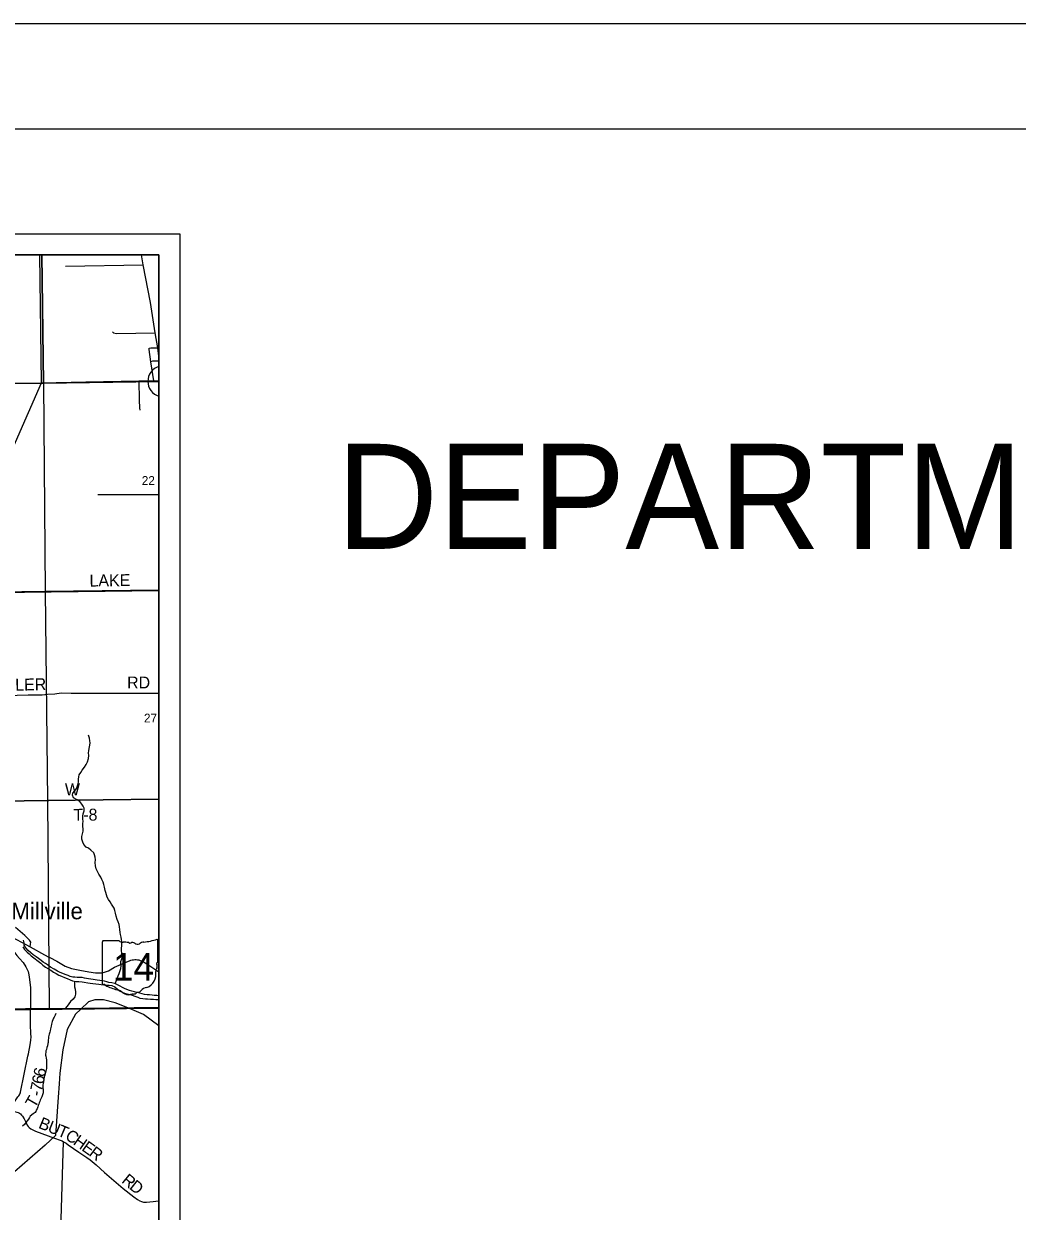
# Model space of a CAD drawing. Extents: x 0 to 34, y 0 to 22.
# Drawn here: x 8.26 to 12.99, y 16.35 to 22 of the extents above; entities that cross this region are included whole.
import ezdxf

# ---------------------------------------------------------------- set-up
doc = ezdxf.new("R2010")
doc.units = 0
for name, color, linetype in [('GM_X_County_Road', 7, 'Continuous'), ('GM_X_Minor_River', 7, 'Continuous'), ('GM_X_Rail_Line', 7, 'Continuous'), ('GM_X_Section', 7, 'Continuous'), ('GM_X_Section_Text', 7, 'Continuous'), ('GM_X_State_Location', 7, 'Continuous'), ('GM_X_State_Route', 7, 'Continuous'), ('GM_X_State_Shield', 7, 'Continuous'), ('GM_X_Township_Road', 7, 'Continuous'), ('GM_X_Township_Road_Text', 7, 'Continuous'), ('GM_X_Unincorporated_Text', 7, 'Continuous'), ('SH_Border', 7, 'Continuous'), ('SH_Cut_Line', 7, 'Continuous'), ('SH_Data', 7, 'Continuous'), ('SH_Text', 7, 'Continuous')]:
    doc.layers.add(name, color=color, linetype=linetype)

msp = doc.modelspace()

# ---------------------------------------------------------------- linework, layer by layer
at = {"layer": 'GM_X_County_Road'}
for points in [[(8.9, 20.4176), (8.8952, 20.4576), (8.8827, 20.5279), (8.8607, 20.6726), (8.8255, 20.8525), (8.8168, 20.9)], [(7.8996, 19.2895), (8.1438, 19.8412), (8.341, 20.2911)], [(8.2872, 17.6056), (8.2893, 17.6184), (8.2907, 17.6268), (8.2847, 17.6373), (8.2615, 17.6593), (8.2181, 17.6976)]]:
    msp.add_lwpolyline(points, dxfattribs=at)
at = {"layer": 'GM_X_Minor_River'}
for points in [[(8.6919, 17.4296), (8.7068, 17.4673), (8.7112, 17.4787), (8.7159, 17.4921), (8.7192, 17.5024), (8.7201, 17.5153), (8.7192, 17.5252), (8.719, 17.5358), (8.7233, 17.5477), (8.7269, 17.561), (8.7244, 17.5754), (8.7215, 17.5875), (8.7221, 17.5982), (8.7238, 17.6096), (8.7244, 17.6202), (8.7239, 17.6305), (8.7222, 17.6403), (8.7205, 17.6506), (8.718, 17.6634), (8.7167, 17.674), (8.715, 17.6873), (8.7132, 17.7002), (8.7111, 17.7112), (8.7071, 17.7244), (8.7024, 17.7346), (8.6968, 17.7519), (8.6943, 17.7652), (8.691, 17.7784), (8.6871, 17.7886), (8.6812, 17.7988), (8.675, 17.8086), (8.6684, 17.8187), (8.661, 17.83), (8.6543, 17.8416), (8.6503, 17.8526), (8.6471, 17.8632), (8.6443, 17.873), (8.6414, 17.8885), (8.6385, 17.9025), (8.6349, 17.9131), (8.629, 17.9259), (8.6243, 17.9361), (8.6149, 17.9511), (8.6086, 17.9632), (8.6023, 17.9767), (8.5983, 17.99), (8.5969, 18.0063), (8.5982, 18.02), (8.5969, 18.0321), (8.5944, 18.0431), (8.5904, 18.0529), (8.5758, 18.0659), (8.5646, 18.0741), (8.5547, 18.0804), (8.5427, 18.0924), (8.5376, 18.104), (8.5339, 18.118), (8.5337, 18.1306), (8.5362, 18.1424), (8.539, 18.1553), (8.5399, 18.1675), (8.5386, 18.1785), (8.5388, 18.1922), (8.5394, 18.2024), (8.5388, 18.215), (8.5389, 18.2279), (8.5403, 18.2382), (8.5438, 18.253), (8.544, 18.2648), (8.5404, 18.2746), (8.5342, 18.2844), (8.5234, 18.2975), (8.5111, 18.3053), (8.4942, 18.3141), (8.4887, 18.3266), (8.4904, 18.3368), (8.5005, 18.348), (8.5079, 18.3592), (8.5134, 18.3714), (8.5155, 18.3809), (8.5169, 18.3912), (8.5178, 18.4041), (8.5184, 18.414), (8.5212, 18.4243), (8.5279, 18.4358), (8.5357, 18.4458), (8.5461, 18.4601), (8.5535, 18.4731), (8.5605, 18.4857), (8.5655, 18.5014), (8.566, 18.5155), (8.5655, 18.528), (8.566, 18.539), (8.5689, 18.5493), (8.5721, 18.5646), (8.5726, 18.5756), (8.5717, 18.5866), (8.5692, 18.5979), (8.5644, 18.613)], [(8.252, 17.6048), (8.2598, 17.5924), (8.2726, 17.5793), (8.2826, 17.5712)], [(8.2665, 17.6005), (8.2595, 17.6137), (8.2581, 17.6239), (8.2564, 17.6368)], [(8.9, 17.3713), (8.8902, 17.3727), (8.8785, 17.374), (8.8678, 17.375), (8.856, 17.3759), (8.8446, 17.3773), (8.8317, 17.3789), (8.8203, 17.381), (8.8088, 17.3839), (8.7959, 17.3871), (8.7848, 17.3907), (8.7718, 17.3943), (8.76, 17.3975), (8.7482, 17.4019), (8.7371, 17.4062), (8.7275, 17.411), (8.716, 17.4173), (8.7037, 17.4243), (8.6907, 17.4302), (8.6763, 17.4333), (8.6626, 17.4358), (8.653, 17.4379), (8.6416, 17.4415), (8.6309, 17.4432), (8.6191, 17.4446), (8.6069, 17.4466), (8.5967, 17.448), (8.5868, 17.4497), (8.5757, 17.4514), (8.5655, 17.4528), (8.5559, 17.4545), (8.5457, 17.4566), (8.5358, 17.4584), (8.5255, 17.4593), (8.5118, 17.4599), (8.5004, 17.4601), (8.4902, 17.461), (8.478, 17.4643), (8.4684, 17.4679), (8.4539, 17.4737), (8.4428, 17.4785), (8.4306, 17.4832), (8.4168, 17.4887), (8.4015, 17.4987), (8.3846, 17.5087), (8.37, 17.5187), (8.3604, 17.5253), (8.35, 17.5316), (8.3393, 17.5406), (8.3269, 17.5502), (8.3154, 17.5573), (8.302, 17.5673), (8.2904, 17.5766), (8.2781, 17.5878), (8.2665, 17.6005)], [(8.2826, 17.5712), (8.2922, 17.5626), (8.3049, 17.5525), (8.326, 17.5362), (8.338, 17.5273), (8.3484, 17.5176), (8.361, 17.509), (8.3752, 17.5009), (8.3852, 17.4939), (8.3983, 17.485), (8.4105, 17.4779), (8.4239, 17.471), (8.4373, 17.4655), (8.4507, 17.4596), (8.4633, 17.4545), (8.4782, 17.4483), (8.4893, 17.4436), (8.5057, 17.4404), (8.5194, 17.4395), (8.5353, 17.4386), (8.5452, 17.4376), (8.5624, 17.4341), (8.5734, 17.432), (8.586, 17.4307), (8.6008, 17.4291), (8.6137, 17.4278), (8.6255, 17.4257), (8.6381, 17.4236), (8.6537, 17.4227), (8.6639, 17.4221), (8.6769, 17.4208), (8.6902, 17.415), (8.7026, 17.4038), (8.7122, 17.3952), (8.7256, 17.3897), (8.737, 17.385), (8.7485, 17.3814), (8.763, 17.3774), (8.7737, 17.3746), (8.7859, 17.3702), (8.8008, 17.3648), (8.8103, 17.3615), (8.8237, 17.3587), (8.8366, 17.3578), (8.8461, 17.3571), (8.8609, 17.3563), (8.8753, 17.3557), (8.8852, 17.3551), (8.8974, 17.3538), (8.9, 17.3532)], [(8.4981, 17.4419), (8.4985, 17.4152), (8.501, 17.4031), (8.5031, 17.3899), (8.5025, 17.38), (8.4997, 17.3674), (8.4919, 17.3566), (8.4799, 17.3443), (8.471, 17.3331), (8.4629, 17.322), (8.4539, 17.3112)], [(8.4099, 17.2872), (8.4098, 17.2871), (8.4066, 17.2795), (8.4018, 17.2702), (8.3982, 17.2652), (8.3953, 17.2583), (8.3924, 17.2502), (8.3903, 17.2426), (8.3896, 17.2376), (8.3876, 17.2269), (8.3854, 17.2212), (8.3844, 17.2151), (8.3827, 17.2052), (8.3814, 17.1987), (8.3785, 17.1895), (8.376, 17.183), (8.3754, 17.1769), (8.3748, 17.1689), (8.3734, 17.1624), (8.3731, 17.1563), (8.3725, 17.1502), (8.3715, 17.1441), (8.3706, 17.1345), (8.3673, 17.1257), (8.3645, 17.1162), (8.3627, 17.1097), (8.3614, 17.102), (8.3604, 17.0952), (8.3609, 17.0891), (8.3618, 17.0842), (8.3638, 17.0758), (8.3652, 17.0667), (8.3657, 17.0595), (8.365, 17.0382), (8.3653, 17.0253), (8.3611, 17.0066), (8.3593, 17.0016), (8.3568, 16.9939), (8.3543, 16.9859), (8.3527, 16.9729), (8.3503, 16.9615), (8.3493, 16.9554), (8.3476, 16.9462), (8.347, 16.9397), (8.3474, 16.9348), (8.3488, 16.9257), (8.3501, 16.9185), (8.3487, 16.9097), (8.3427, 16.8902), (8.3387, 16.8821), (8.3347, 16.8752), (8.3329, 16.8694), (8.3308, 16.8625), (8.3282, 16.8564), (8.325, 16.8499), (8.3232, 16.8434), (8.3204, 16.8346), (8.3167, 16.8272), (8.3146, 16.8219), (8.3113, 16.8169), (8.3023, 16.8098), (8.2878, 16.7988), (8.2841, 16.7931), (8.279, 16.7853), (8.2664, 16.768), (8.2598, 16.7587), (8.2509, 16.7513)]]:
    msp.add_lwpolyline(points, dxfattribs=at)
at = {"layer": 'GM_X_Rail_Line'}
for points in [[(7.4754, 17.3006), (8.2882, 17.3064), (8.9, 17.3138), (8.9, 20.9), (5.4984, 20.9)], [(8.5286, 17.3089), (8.5035, 17.2853), (8.4632, 17.2119), (8.4437, 17.114), (8.4289, 17.004), (8.426, 16.9527), (8.4215, 16.8896), (8.4085, 16.7064), (8.3593, 16.6612), (8.0289, 16.3753)], [(8.76, 17.3117), (8.6923, 17.3381), (8.6373, 17.3524), (8.595, 17.353), (8.5653, 17.3434), (8.5286, 17.3089)], [(8.9, 17.2297), (8.8277, 17.2837), (8.76, 17.3117)]]:
    msp.add_lwpolyline(points, dxfattribs=at)
msp.add_lwpolyline([(5.5619, 14.1), (8.9, 14.1), (8.9, 17.3138), (8.2882, 17.3064), (7.4754, 17.3006), (7.4757, 17.0495), (7.4723, 16.4951), (7.4818, 15.827), (7.482, 15.8179), (7.4834, 15.2992), (7.3416, 15.297), (6.5709, 15.2859), (6.3575, 15.2833), (5.5569, 15.2761), (5.5579, 15.2049), (5.5588, 15.1747), (5.5581, 14.9676), (5.5583, 14.9347), (5.5595, 14.6439), (5.5615, 14.2414), (5.5608, 14.205)], close=True, dxfattribs=at)
at = {"layer": 'GM_X_Section'}
for points in [[(7.3448, 20.2776), (8.3505, 20.2885), (8.3591, 19.2972), (7.3562, 19.2826)], [(7.3562, 19.2826), (8.3591, 19.2972), (8.3698, 18.3026), (7.3737, 18.2882)], [(7.3737, 18.2882), (8.3698, 18.3026), (8.3784, 17.3112), (7.4756, 17.2983), (7.3918, 17.2975)]]:
    msp.add_lwpolyline(points, close=True, dxfattribs=at)
at = {"layer": 'GM_X_State_Route'}
for points in [[(8.5527, 20.295), (8.8047, 20.2996), (8.8761, 20.3006), (8.9, 20.2998)], [(6.5764, 20.2689), (6.689, 20.2704), (8.341, 20.2911), (8.5527, 20.295)], [(7.9769, 17.6625), (7.989, 17.6724), (8.0066, 17.6879), (8.0232, 17.6976), (8.0383, 17.7032), (8.0648, 17.7086), (8.0877, 17.7051), (8.1129, 17.6987), (8.1806, 17.6629), (8.2872, 17.6056)], [(8.2872, 17.6056), (8.3557, 17.5677), (8.3765, 17.5566), (8.3803, 17.5546)], [(8.3803, 17.5546), (8.4144, 17.5364), (8.4543, 17.5134), (8.4846, 17.5025), (8.5246, 17.4937), (8.5669, 17.4867), (8.5978, 17.4819), (8.6132, 17.481), (8.6301, 17.4817), (8.6458, 17.4859), (8.6596, 17.4916), (8.6883, 17.5077), (8.7475, 17.5333), (8.7598, 17.5385), (8.7663, 17.5411), (8.7729, 17.5428), (8.7791, 17.5438), (8.7857, 17.5444), (8.7923, 17.5445), (8.7987, 17.544), (8.8056, 17.5426), (8.8116, 17.5407), (8.8216, 17.5364), (8.8424, 17.5242), (8.9, 17.486)]]:
    msp.add_lwpolyline(points, dxfattribs=at)
at = {"layer": 'GM_X_State_Shield'}
for p, q in [((8.631, 17.6295), (8.631, 17.4294)), ((8.7109, 17.633), (8.6336, 17.633)), ((8.8947, 17.5332), (8.8947, 17.6379)), ((8.8947, 17.5333), (8.8947, 17.5332))]:
    msp.add_line(p, q, dxfattribs=at)
for points in [[(8.343, 20.9), (7.3363, 20.9), (7.3448, 20.2776), (8.3505, 20.2885)], [(8.9, 20.2971), (8.9, 20.9), (8.343, 20.9), (8.3505, 20.2885)], [(8.9, 19.3038), (8.9, 20.2971), (8.3505, 20.2885), (8.3591, 19.2972)], [(8.9, 18.3087), (8.9, 19.3038), (8.3591, 19.2972), (8.3698, 18.3026)], [(8.9, 17.3185), (8.9, 18.3087), (8.3698, 18.3026), (8.3784, 17.3112), (8.4281, 17.3119)]]:
    msp.add_lwpolyline(points, close=True, dxfattribs=at)
for centre, radius, start, end in [((8.8008, 17.9058), 0.2796, 275.8445, 288.9065), ((8.8918, 17.6383), 0.00294, 351.8621, 97.738), ((8.6341, 17.6299), 0.00305, 98.1301, 188.1301), ((8.7292, 17.6562), 0.0296, 231.6195, 271.1119), ((8.7391, 17.5206), 0.1064, 80.4867, 94.9883), ((8.7632, 17.631), 0.00855, 219.7921, 297.1024), ((8.7758, 17.6078), 0.0178, 54.4667, 119.1411), ((8.7987, 17.6396), 0.0214, 233.8562, 294.8282), ((8.8365, 17.5718), 0.0563, 97.3462, 120.7689), ((8.894, 17.5255), 0.00454, 107.944, 210.337), ((8.8916, 17.5328), 0.00314, 289.6038, 7.7341), ((8.8165, 17.4761), 0.0699, 292.3089, 8.9858), ((8.9052, 17.4894), 0.0198, 136.8065, 186.9296), ((8.8651, 17.5123), 0.0273, 340.033, 23.6496), ((8.6341, 17.429), 0.00308, 171.9584, 258.3066), ((8.6346, 17.4494), 0.0235, 267.339, 280.6039), ((8.6394, 17.4178), 0.00848, 29.7484, 93.2717), ((8.7464, 17.5976), 0.2019, 240.4129, 257.1985), ((8.6862, 17.3395), 0.0632, 47.1842, 75.836), ((8.7546, 17.4169), 0.0401, 230.7004, 286.2918), ((8.7777, 17.3477), 0.0329, 85.6951, 111.2099), ((8.7807, 17.4019), 0.0214, 268.777, 315.5493), ((8.8, 17.3825), 0.00601, 65.7517, 132.6484), ((8.7974, 17.41), 0.0226, 282.8732, 323.2771), ((8.8459, 17.3732), 0.0383, 94.4031, 142.5768)]:
    msp.add_arc(centre, radius, start, end, dxfattribs=at)
at = {"layer": 'GM_X_Township_Road'}
for p, q in [((8.341, 20.2911), (8.3333, 20.9)), ((8.4556, 20.846), (8.8255, 20.8525)), ((8.9, 19.7567), (8.6096, 19.7567)), ((7.8996, 19.2895), (8.9, 19.302)), ((7.9296, 18.2972), (8.3771, 18.3024)), ((8.4566, 18.3034), (8.9, 18.3104))]:
    msp.add_line(p, q, dxfattribs=at)
for points in [[(8.6795, 20.5327), (8.684, 20.5282), (8.6982, 20.5258), (8.8827, 20.5279)], [(8.8761, 20.3006), (8.8625, 20.3908), (8.8534, 20.4492), (8.8541, 20.4548), (8.8614, 20.4576), (8.8952, 20.4576)], [(8.9, 20.3938), (8.8694, 20.3932), (8.8625, 20.3908)], [(8.8047, 20.2996), (8.8061, 20.2077), (8.8085, 20.1715), (8.8096, 20.16)], [(7.9779, 18.7942), (8.1182, 18.7998), (8.2774, 18.8045), (8.3451, 18.8044), (8.3694, 18.8075), (8.4051, 18.8098), (8.435, 18.8149), (8.4822, 18.8129), (8.8446, 18.8126), (8.9, 18.8124)], [(8.3771, 18.3024), (8.4507, 18.3033), (8.4566, 18.3034)], [(8.1999, 17.635), (8.1999, 17.6177), (8.2024, 17.6018), (8.21, 17.5833), (8.2236, 17.5641), (8.2368, 17.5495), (8.2543, 17.53), (8.2672, 17.5093), (8.2777, 17.4874), (8.2804, 17.4715), (8.2846, 17.4491), (8.2887, 17.4097), (8.2884, 17.3058)], [(8.1834, 16.8228), (8.2289, 16.8904), (8.2334, 16.8961), (8.2367, 16.9011), (8.239, 16.9053), (8.2408, 16.9097), (8.2418, 16.9133), (8.2771, 17.0838), (8.2795, 17.0956), (8.2874, 17.1388), (8.2907, 17.1603), (8.2914, 17.1653), (8.2917, 17.1711), (8.2916, 17.177), (8.2906, 17.1902), (8.2888, 17.2353), (8.2886, 17.2721), (8.2884, 17.3058)], [(8.1834, 16.8228), (8.202, 16.822), (8.2077, 16.8214), (8.2128, 16.8204), (8.2245, 16.8183), (8.2305, 16.816), (8.2364, 16.8131), (8.2416, 16.8093), (8.2468, 16.8042), (8.2508, 16.7988), (8.2589, 16.786), (8.268, 16.7675), (8.2735, 16.7562), (8.2775, 16.7505), (8.2827, 16.745), (8.2908, 16.7384), (8.3127, 16.728), (8.4034, 16.6946), (8.431, 16.6848), (8.4391, 16.6814), (8.4462, 16.6768)], [(8.4337, 16.2122), (8.4332, 16.2555), (8.4462, 16.6768)], [(8.4462, 16.6768), (8.4587, 16.6698), (8.4687, 16.6626), (8.5197, 16.6278), (8.558, 16.6016), (8.5733, 16.5915), (8.6012, 16.5679), (8.6415, 16.5305), (8.7302, 16.4547), (8.7809, 16.4141), (8.7982, 16.4018), (8.8088, 16.3957), (8.8177, 16.3923), (8.8275, 16.3902), (8.8411, 16.3891), (8.873, 16.3923), (8.8981, 16.396), (8.9, 16.3961)]]:
    msp.add_lwpolyline(points, dxfattribs=at)
at = {"layer": 'GM_X_Unincorporated_Text'}
msp.add_line((8.9, 20.2265), (8.9, 20.3685), dxfattribs=at)
msp.add_arc((8.9222, 20.2975), 0.0744, 107.3731, 252.6269, dxfattribs=at)
at = {"layer": 'SH_Border'}
msp.add_lwpolyline([(1.5, 21.5), (33.5, 21.5), (33.5, 0.5), (1.5, 0.5)], close=True, dxfattribs=at)
at = {"layer": 'SH_Cut_Line'}
msp.add_lwpolyline([(0, 0), (34, 0), (34, 22), (0, 22)], close=True, dxfattribs=at)
for points in [[(7.4754, 17.3006), (8.2882, 17.3064), (8.9, 17.3138), (8.9, 20.9), (2.1, 20.9)], [(2.1, 14.1), (8.9, 14.1), (8.9, 17.3138), (8.2882, 17.3064), (7.4754, 17.3006)]]:
    msp.add_lwpolyline(points, dxfattribs=at)
at = {"layer": 'SH_Data'}
for p, q in [((2, 21), (9, 21)), ((9, 21), (9, 14)), ((2.1, 20.9), (8.9, 20.9)), ((8.9, 20.9), (8.9, 14.1))]:
    msp.add_line(p, q, dxfattribs=at)

# ---------------------------------------------------------------- texts
at = {"layer": 'GM_X_Section_Text'}
for s, p in [('22', (8.8189, 19.8045)), ('27', (8.8293, 18.6734))]:
    msp.add_text(s, height=0.04186, rotation=0, dxfattribs=at).set_placement(p)
at = {"layer": 'GM_X_State_Location'}
msp.add_text('14', height=0.000189, rotation=0, dxfattribs=at).set_placement((8.7122, 17.5024))
for s in ['s', 'r']:
    msp.add_text(s, height=0.000189, dxfattribs=at).set_placement((8.7599, 17.5161))
at = {"layer": 'GM_X_State_Shield'}
msp.add_text('14', height=0.13184, dxfattribs=at).set_placement((8.6816, 17.4435))
at = {"layer": 'GM_X_Township_Road_Text'}
for s, height, rotation, p in [('LAKE', 0.05682, 0.7743, (8.5702, 19.3203)), ('ROLLER', 0.05682, 1.4167, (8.0606, 18.8203)), ('RD', 0.05682, 0, (8.7489, 18.8353)), ('W', 0.0568, 0, (8.453, 18.3261)), ('T-8', 0.05682, 0.4781, (8.4939, 18.2051)), ('6', 0.0568, 78.4257, (8.357, 16.9823)), ('7', 0.0568, 78.0481, (8.3426, 16.9134)), ('6', 0.0568, 78.3492, (8.3499, 16.9479)), ('-', 0.0568, 79.8624, (8.3386, 16.8909)), ('T', 0.0568, 59.9542, (8.3099, 16.834)), ('B', 0.0568, 337.9884, (8.3231, 16.7441)), ('U', 0.0568, 337.9848, (8.3664, 16.7266)), ('T', 0.0568, 337.273, (8.4125, 16.708)), ('C', 0.0568, 326.9259, (8.4494, 16.6928)), ('H', 0.0568, 324.7033, (8.488, 16.6677)), ('E', 0.0568, 324.6492, (8.5288, 16.6388)), ('R', 0.0568, 322.9826, (8.5631, 16.6145)), ('R', 0.0568, 320.8166, (8.7189, 16.4857)), ('D', 0.0568, 321.7054, (8.7558, 16.4556))]:
    msp.add_text(s, height=height, rotation=rotation, dxfattribs=at).set_placement(p)
at = {"layer": 'GM_X_Unincorporated_Text'}
msp.add_text('Millville', height=0.07898, rotation=0, dxfattribs=at).set_placement((8.198, 17.7362))
at = {"layer": 'SH_Text'}
msp.add_text('DEPARTMENT OF TRANSPORTATION', height=0.5, dxfattribs=at).set_placement((9.7466, 19.5))

doc.saveas('drawing.dxf')
